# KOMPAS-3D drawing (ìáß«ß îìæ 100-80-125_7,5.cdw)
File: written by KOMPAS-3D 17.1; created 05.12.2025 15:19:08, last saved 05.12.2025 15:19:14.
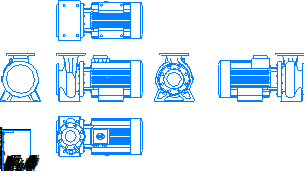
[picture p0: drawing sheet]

Sheet 1: A4, portrait

Title block, sheet 1: name: Насос МНС / 100-80-125_7,5; material: Сталь 10  ГОСТ 1050-88; mass: 185,42; sheets: 1; sheet format: A4

Views: Вид 1, Спереди, Проекционный вид 2, Проекционный вид 3, Проекционный вид 4, Проекционный вид 5, Проекционный вид 6
Referenced files in \\adlc.lan\data\АДЛ_ПКД\3D-модели\ADL production\Насосы ГРАНПАМП\Насосы ГРАНПАМП серии МНС\KOMPAS 3D\: Насос МНС 100-80-125_7,5.m3d
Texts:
  Andrey
  АДЛ
Dimensions and other numbers on the sheet: 1:1; 1; 100-80-125_7,5; 185,42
